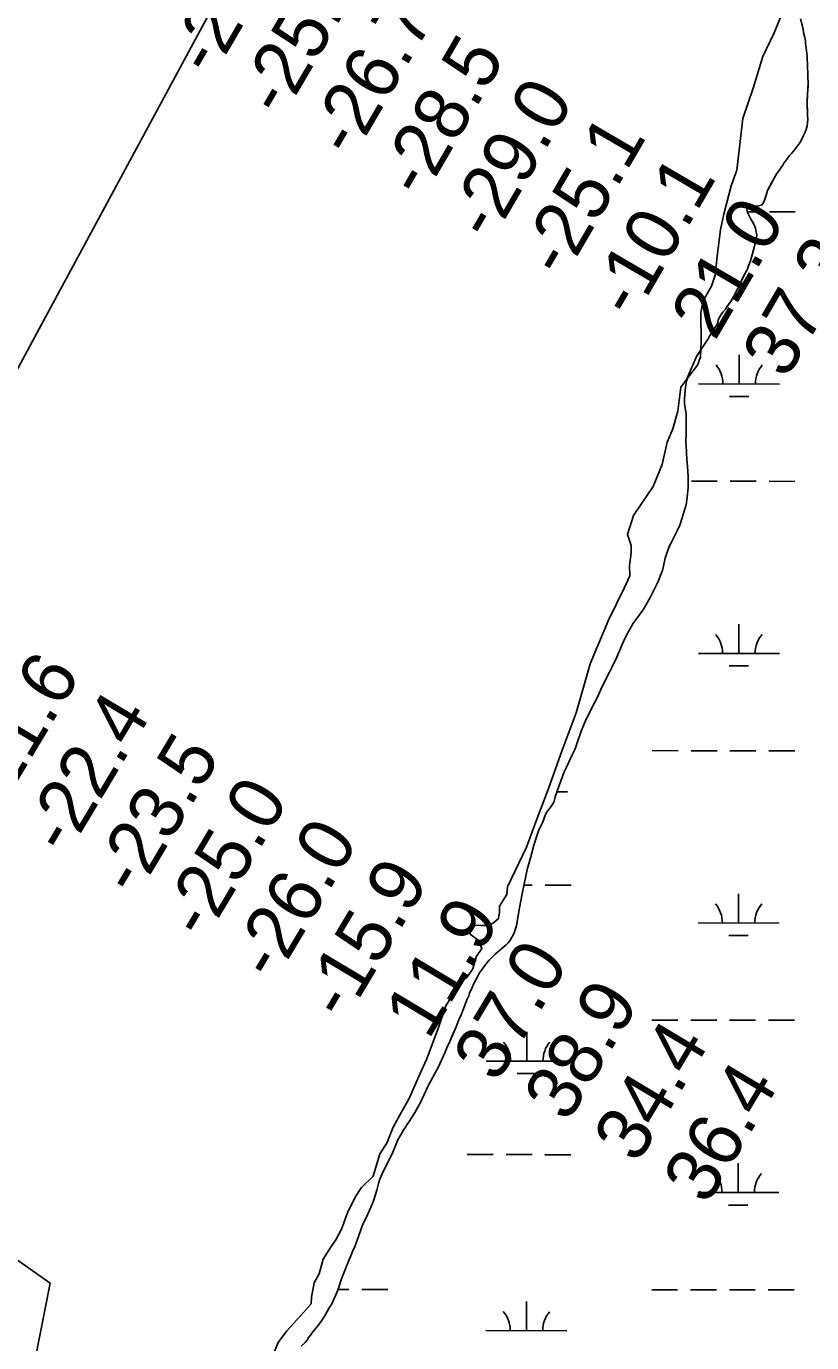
# Model space of a CAD drawing. Extents: x 3148686 to 3186545, y 916144 to 941516.
# Drawn here: x 3158993 to 3159963, y 925065 to 926690 of the extents above; entities that cross this region are included whole.
import ezdxf

# ---------------------------------------------------------------- set-up
doc = ezdxf.new("R2010")
doc.units = 0
for name, color, linetype in [('V-RIVR-EDGE', 7, 'Continuous'), ('V-RIVR-RANG', 7, 'Continuous'), ('V-SITE-VEGE', 7, 'Continuous'), ('V-TOPO-BNDY', 7, 'Continuous'), ('V-WETL-SWMP', 7, 'Continuous')]:
    doc.layers.add(name, color=color, linetype=linetype)

msp = doc.modelspace()

# ---------------------------------------------------------------- linework, layer by layer
at = {"layer": 'V-RIVR-EDGE'}
for points in [[(3159740.5, 926039.6), (3159740.2, 926049), (3159735.7, 926062.5), (3159743.4, 926085.9), (3159767.5, 926121.5), (3159778.5, 926148.8), (3159785, 926176.5), (3159792, 926193), (3159798.2, 926214.6), (3159801.6, 926244.4), (3159815.1, 926262.4), (3159822.1, 926271.2), (3159825.8, 926281.5), (3159826.7, 926299.8), (3159826.5, 926336.3), (3159829.3, 926350.9), (3159839.7, 926368.9), (3159844, 926382.6), (3159846.5, 926405.4), (3159850.8, 926438.9), (3159855.4, 926459.3), (3159863.7, 926492.8), (3159870.8, 926512), (3159878.3, 926575.9), (3159891.1, 926613.3), (3159902.8, 926652.6), (3159916.9, 926681.5), (3159931.9, 926718)], [(3159292.8, 925037.2), (3159304.4, 925065.2), (3159315.1, 925079.5), (3159332.2, 925098.3), (3159345, 925112.6), (3159345.7, 925121.1), (3159349, 925138.5), (3159355.2, 925149.7), (3159360.1, 925167.7), (3159369.9, 925183.5), (3159375.7, 925191.7), (3159382.7, 925204.8), (3159390.1, 925224.9), (3159399.3, 925244.3), (3159407.5, 925256.5), (3159421.9, 925270.2), (3159430.1, 925297.9), (3159438.7, 925311.2), (3159446.4, 925330.7), (3159457.7, 925351.1), (3159466.3, 925366.3), (3159477.6, 925392.5), (3159487.7, 925414.4), (3159501.8, 925452.4), (3159511.6, 925480.7), (3159523.8, 925500.5), (3159527.8, 925509.9), (3159537.3, 925515.4), (3159544.9, 925526.3), (3159548.9, 925541.2), (3159555.9, 925551.2), (3159550.8, 925562.2), (3159542, 925568.6), (3159540.2, 925574.1), (3159543.8, 925580.2), (3159555.4, 925579.9), (3159564.5, 925579.6), (3159570.3, 925583.2), (3159576.4, 925588.4), (3159577.7, 925596), (3159577.7, 925603.6), (3159586.6, 925618.2), (3159587.5, 925627.3), (3159611.1, 925676.3), (3159624.9, 925714.3), (3159637.7, 925747.8), (3159655.2, 925796.2), (3159672.4, 925842.4), (3159689.9, 925902.7), (3159712.3, 925956.5), (3159731.9, 925996.1), (3159738.6, 926011.3), (3159738.3, 926024.1), (3159740.5, 926039.6)]]:
    msp.add_lwpolyline(points, dxfattribs=at)
at = {"layer": 'V-SITE-VEGE'}
for points in [[(3159949.7, 926699), (3159952.8, 926686), (3159953.4, 926682), (3159954.9, 926675.8), (3159955.5, 926672.2), (3159955.5, 926668.6), (3159956.5, 926663), (3159957.6, 926652.8), (3159957.6, 926648.6), (3159958.1, 926643.8), (3159958.1, 926639), (3159958.5, 926631.8), (3159958.6, 926627.2), (3159959, 926620.2), (3159958.6, 926611.8), (3159958.3, 926606.3), (3159957.9, 926597.9), (3159957.6, 926591.9), (3159958.2, 926582.3), (3159958.2, 926579.3), (3159958.5, 926575.5), (3159958.3, 926570.1), (3159957.9, 926566.7), (3159956.7, 926562.3), (3159954.9, 926558.3), (3159953.2, 926555.1), (3159950.2, 926548.9), (3159948.6, 926546), (3159946.4, 926542.6), (3159943.3, 926538.8), (3159940.7, 926535.4), (3159935.7, 926529.6), (3159933.3, 926526.5), (3159929.1, 926520.7), (3159927.6, 926518.1), (3159925.6, 926515.5), (3159923.2, 926511.7), (3159920.4, 926508), (3159917, 926502.4), (3159908.9, 926486.8), (3159907, 926481.3), (3159905, 926475.1), (3159903.4, 926471.3), (3159901.2, 926469.1), (3159897.6, 926468.1), (3159894.2, 926467.7), (3159890.6, 926468), (3159886.6, 926468.2), (3159883.2, 926463.2), (3159884.1, 926459.8), (3159885.9, 926456.6), (3159887.7, 926452.6), (3159891.7, 926445.6), (3159893.8, 926440.4), (3159894.8, 926436), (3159895.4, 926432.2), (3159895.2, 926429), (3159893.5, 926421.6), (3159889.8, 926407.4), (3159887.6, 926400), (3159886.4, 926396.8), (3159885.2, 926393.9), (3159883.9, 926390.1), (3159882.3, 926386.9), (3159876.9, 926376.9), (3159873.8, 926369.3), (3159872, 926366.2)], [(3159872, 926366.2), (3159870.4, 926363.2), (3159867, 926356.4), (3159863.7, 926351), (3159858.9, 926344), (3159857.1, 926340.9), (3159853.7, 926336.9), (3159852, 926334.5), (3159850.2, 926331.7), (3159848, 926327.5), (3159847.4, 926323.7), (3159846, 926320.9), (3159844.1, 926318.1), (3159840.9, 926312.6), (3159837.3, 926307), (3159835.5, 926304), (3159827.1, 926291.7), (3159821.2, 926282), (3159819.6, 926278.1), (3159817.7, 926274.5), (3159816.4, 926271.4), (3159814.8, 926268), (3159810.1, 926256.3), (3159808.8, 926251.5), (3159807.5, 926244.8), (3159806.2, 926230.2), (3159806.1, 926226.6), (3159806.3, 926223.4), (3159808.2, 926211.3), (3159808.4, 926206.5), (3159808.1, 926203.3), (3159808.2, 926187.8), (3159808, 926176), (3159808.4, 926172.5), (3159808.6, 926163.5), (3159809.2, 926154.7), (3159809.6, 926151.5), (3159810.8, 926134.1), (3159810.6, 926120.6), (3159810, 926112.2), (3159809.5, 926108.3), (3159808.1, 926099.2), (3159807.2, 926095.3), (3159803.5, 926082.8), (3159800.6, 926074.1), (3159797.3, 926067), (3159789.6, 926052.2), (3159787.4, 926047.4), (3159786, 926044), (3159784.8, 926040.7), (3159782.3, 926033), (3159781, 926027.3), (3159780.3, 926023.1), (3159779, 926018.1), (3159777.2, 926013.2), (3159773.7, 926004.3), (3159763.8, 925984.7), (3159758.4, 925975), (3159755.6, 925970.4), (3159750.7, 925963.2), (3159748.7, 925960.3), (3159746.5, 925957.7), (3159742.5, 925951.9), (3159738.2, 925944.9), (3159736.1, 925940.9), (3159732.6, 925934), (3159729.2, 925926.6), (3159722.5, 925911.1), (3159716.7, 925899.2), (3159713.7, 925892.4), (3159704.3, 925873.9), (3159700.1, 925864.6), (3159697.1, 925858.2), (3159695, 925854.4), (3159687.7, 925840.3), (3159683.7, 925831.7), (3159678.8, 925819.5), (3159673, 925802.9), (3159671, 925798), (3159667.7, 925790.6), (3159661.2, 925776.8), (3159658.1, 925770.1), (3159656.5, 925766), (3159654.8, 925761.3), (3159653.6, 925758.5), (3159649.2, 925746.8), (3159646.5, 925738.6), (3159645.1, 925732.9), (3159643.8, 925730.1), (3159641.1, 925726.3), (3159638.5, 925723.1), (3159636, 925719.2), (3159633.8, 925714.6), (3159631.5, 925708.5), (3159626, 925696.6), (3159620.3, 925678.7), (3159617.4, 925667.8), (3159613.8, 925656), (3159612.2, 925650.4), (3159608.8, 925632.7), (3159605.7, 925618.8)], [(3159605.7, 925618.8), (3159602.3, 925601.6), (3159600.1, 925587), (3159598.8, 925579.5), (3159596.4, 925571.8), (3159594.5, 925567.7), (3159592.7, 925564.5), (3159590.4, 925561), (3159588.5, 925558.4), (3159586.1, 925555.7), (3159572.6, 925544.3), (3159565, 925537), (3159562.2, 925533.7), (3159553.2, 925521.3), (3159551.3, 925518.1), (3159545.7, 925507.3), (3159543.8, 925503.2), (3159540.9, 925496.1), (3159539.8, 925492.9), (3159537.9, 925488.8), (3159530.2, 925469.5), (3159527.4, 925463.2), (3159524.1, 925454.8), (3159515.6, 925434.5), (3159513.7, 925430.6), (3159510.4, 925422.7), (3159504.2, 925409.1), (3159502, 925404.6), (3159498.2, 925397.9), (3159489.3, 925380.9), (3159484.5, 925371), (3159480.4, 925362), (3159477, 925355.4), (3159472.7, 925348), (3159470.8, 925344.9), (3159459.3, 925327.3), (3159452.3, 925315.2), (3159445, 925297.7), (3159434.4, 925276.7), (3159430.1, 925266.8), (3159428.2, 925261.1), (3159426.2, 925253), (3159422.9, 925242.5), (3159420.7, 925236.6), (3159413, 925218.9), (3159409.1, 925210.9), (3159398.9, 925183.2), (3159397.1, 925179.2), (3159394.2, 925171.8), (3159392.5, 925168.1), (3159382.7, 925143.5), (3159379.8, 925134.6), (3159377.1, 925127.7), (3159370.3, 925112.1), (3159367.5, 925107.7), (3159362.5, 925098.6), (3159357.9, 925091.6), (3159353.7, 925085.9), (3159347.4, 925078.3), (3159344.6, 925074.4), (3159342.4, 925071.4), (3159340.2, 925067.8), (3159337.9, 925065.2), (3159332.9, 925060.5)]]:
    msp.add_lwpolyline(points, dxfattribs=at)
at = {"layer": 'V-TOPO-BNDY'}
for points in [[(3156122.4, 922098.2), (3156168.8, 922145.8), (3156428.7, 922411), (3156852.6, 922931.2), (3157254.5, 923382.8), (3157305.3, 923439.5), (3157317.3, 923453.1), (3157677.4, 924009.7), (3157746.6, 924116.6), (3157949.7, 924442.8), (3158078.5, 924650.3), (3158117.2, 924712.4), (3158363.3, 925108.2), (3158430.5, 925235.2), (3158537.2, 925435.5), (3158721.6, 925781.3), (3158837.1, 925997.9), (3159006.2, 926311.1), (3159280.9, 926819.7)], [(3160847.8, 924177.7), (3160641.8, 924139.1), (3160353.9, 924087.6), (3159860.3, 924136.3), (3159704.5, 924185.6), (3159392.9, 924289), (3159085.6, 924463), (3159034.9, 924602.9), (3159010.3, 924670.5), (3159009.3, 924692.2), (3159000.3, 924860.7), (3158993.7, 924989.2), (3159003.7, 925042.2), (3159022.8, 925138.1), (3158942.3, 925194.8), (3158717.5, 925353), (3158537.2, 925435.5)]]:
    msp.add_lwpolyline(points, dxfattribs=at)
at = {"layer": 'V-WETL-SWMP'}
for p, q in [((3159883.8, 926460.8), (3159895.1, 926460.8)), ((3159911.1, 926460.8), (3159943.1, 926460.7)), ((3159873.7, 926248.2), (3159873.7, 926284.2)), ((3159823.7, 926248.2), (3159923.7, 926248.1)), ((3159861.7, 926232.8), (3159885.7, 926232.7)), ((3159814.7, 926128.2), (3159846.7, 926128.1)), ((3159862.7, 926128.1), (3159894.7, 926128.1)), ((3159910.7, 926128.1), (3159942.7, 926128)), ((3159873.4, 925915.5), (3159873.4, 925951.5)), ((3159823.4, 925915.6), (3159923.4, 925915.5)), ((3159861.3, 925900.1), (3159885.3, 925900.1)), ((3159766.4, 925795.6), (3159798.4, 925795.5)), ((3159814.4, 925795.5), (3159846.4, 925795.5)), ((3159862.4, 925795.5), (3159894.4, 925795.4)), ((3159910.4, 925795.4), (3159942.4, 925795.4)), ((3159648.6, 925744.9), (3159661.7, 925744.9)), ((3159608.1, 925629.5), (3159618.2, 925629.5)), ((3159634.2, 925629.5), (3159666.2, 925629.5)), ((3159873, 925582.8), (3159873, 925618.8)), ((3159823, 925582.9), (3159923, 925582.8)), ((3159861, 925567.4), (3159885, 925567.4)), ((3159611.4, 925412.3), (3159611.4, 925448.3)), ((3159766, 925462.9), (3159798, 925462.8)), ((3159814, 925462.8), (3159846, 925462.8)), ((3159862, 925462.8), (3159894, 925462.7)), ((3159910, 925462.7), (3159942, 925462.7)), ((3159561.4, 925412.4), (3159661.4, 925412.2)), ((3159599.4, 925396.9), (3159623.4, 925396.9)), ((3159537.9, 925296.9), (3159569.9, 925296.9)), ((3159585.9, 925296.9), (3159617.9, 925296.9)), ((3159633.9, 925296.8), (3159665.9, 925296.8)), ((3159872.7, 925250.2), (3159872.7, 925286.2)), ((3159822.7, 925250.2), (3159922.7, 925250.1)), ((3159860.6, 925234.7), (3159884.6, 925234.7)), ((3159378.2, 925130.6), (3159391.8, 925130.6)), ((3159407.8, 925130.6), (3159439.8, 925130.6)), ((3159765.7, 925130.2), (3159797.7, 925130.2)), ((3159813.7, 925130.2), (3159845.7, 925130.1)), ((3159861.7, 925130.1), (3159893.7, 925130.1)), ((3159909.7, 925130.1), (3159941.7, 925130)), ((3159611, 925079.6), (3159611.1, 925115.6)), ((3159561, 925079.7), (3159661, 925079.6))]:
    msp.add_line(p, q, dxfattribs=at)
for points in [[(3159951, 926693.6), (3159952, 926689.2), (3159952.8, 926686), (3159953.4, 926682), (3159954.9, 926675.8), (3159955.5, 926672.2), (3159955.5, 926668.6), (3159956.5, 926663), (3159957, 926659.2), (3159957.6, 926652.8), (3159957.6, 926648.6), (3159958.1, 926643.8), (3159958.1, 926639), (3159958.5, 926631.8), (3159958.6, 926627.2), (3159959, 926620.2), (3159958.8, 926616.2), (3159958.6, 926611.8), (3159958.3, 926606.3), (3159958.1, 926602.7), (3159957.9, 926597.9), (3159957.6, 926591.9), (3159958, 926586.3), (3159958.2, 926582.3), (3159958.2, 926579.3), (3159958.5, 926575.5), (3159958.3, 926570.1), (3159957.9, 926566.7), (3159956.7, 926562.3), (3159954.9, 926558.3), (3159953.2, 926555.1), (3159950.2, 926548.9), (3159948.6, 926546), (3159946.4, 926542.6), (3159943.3, 926538.8), (3159940.7, 926535.4), (3159938.7, 926533), (3159935.7, 926529.6), (3159933.3, 926526.5), (3159929.1, 926520.7), (3159927.6, 926518.1), (3159925.6, 926515.5), (3159923.2, 926511.7)], [(3159923.2, 926511.7), (3159920.4, 926508), (3159917, 926502.4), (3159914.5, 926497.4), (3159912.3, 926493.4), (3159910.7, 926490.2), (3159908.9, 926486.8), (3159907, 926481.3), (3159905, 926475.1), (3159903.4, 926471.3), (3159901.2, 926469.1), (3159897.6, 926468.1), (3159894.2, 926467.7), (3159890.6, 926468), (3159886.6, 926468.2), (3159883.2, 926463.2), (3159884.1, 926459.8), (3159885.9, 926456.6), (3159887.7, 926452.6), (3159889.7, 926449.2), (3159891.7, 926445.6), (3159893.8, 926440.4), (3159894.8, 926436), (3159895.4, 926432.2), (3159895.2, 926429), (3159894.5, 926425.8), (3159893.5, 926421.6), (3159892.1, 926416.6), (3159890.6, 926410.4), (3159889.8, 926407.4), (3159887.6, 926400), (3159886.4, 926396.8), (3159885.2, 926393.9), (3159883.9, 926390.1), (3159882.3, 926386.9), (3159880.1, 926382.9), (3159876.9, 926376.9), (3159873.8, 926369.3), (3159872, 926366.2), (3159870.4, 926363.2), (3159867, 926356.4), (3159863.7, 926351), (3159861.3, 926347.4), (3159858.9, 926344), (3159857.1, 926340.9), (3159853.7, 926336.9), (3159852, 926334.5), (3159850.2, 926331.7), (3159848, 926327.5), (3159847.4, 926323.7), (3159846, 926320.9), (3159844.1, 926318.1), (3159840.9, 926312.6), (3159837.3, 926307), (3159835.5, 926304), (3159827.1, 926291.7), (3159821.2, 926282), (3159819.6, 926278.1), (3159817.7, 926274.5), (3159816.4, 926271.4), (3159814.8, 926268), (3159810.1, 926256.3), (3159808.8, 926251.5), (3159807.5, 926244.8), (3159806.2, 926230.2), (3159806.1, 926226.6), (3159806.3, 926223.4), (3159808.2, 926211.3), (3159808.4, 926206.5), (3159808.1, 926203.3), (3159808.2, 926187.8), (3159808, 926176), (3159808.4, 926172.5), (3159808.6, 926163.5), (3159809.2, 926154.7), (3159809.6, 926151.5), (3159810.8, 926134.1), (3159810.6, 926120.6), (3159810, 926112.2), (3159809.5, 926108.3), (3159808.1, 926099.2), (3159807.2, 926095.3), (3159803.5, 926082.8), (3159800.6, 926074.1), (3159797.3, 926067), (3159789.6, 926052.2), (3159787.4, 926047.4), (3159786, 926044), (3159784.8, 926040.7), (3159782.3, 926033), (3159781, 926027.3), (3159780.3, 926023.1), (3159779, 926018.1), (3159777.2, 926013.2), (3159773.7, 926004.3), (3159763.8, 925984.7), (3159758.4, 925975), (3159755.6, 925970.4), (3159750.7, 925963.2), (3159748.7, 925960.3), (3159746.5, 925957.7)], [(3159746.5, 925957.7), (3159742.5, 925951.9), (3159738.2, 925944.9), (3159736.1, 925940.9), (3159732.6, 925934), (3159729.2, 925926.6), (3159722.5, 925911.1), (3159716.7, 925899.2), (3159713.7, 925892.4), (3159704.3, 925873.9), (3159700.1, 925864.6), (3159697.1, 925858.2), (3159695, 925854.4), (3159687.7, 925840.3), (3159683.7, 925831.7), (3159678.8, 925819.5), (3159673, 925802.9), (3159671, 925798), (3159667.7, 925790.6), (3159661.2, 925776.8), (3159658.1, 925770.1), (3159656.5, 925766), (3159654.8, 925761.3), (3159653.6, 925758.5), (3159649.2, 925746.8), (3159646.5, 925738.6), (3159645.1, 925732.9), (3159643.8, 925730.1), (3159641.1, 925726.3), (3159638.5, 925723.1), (3159636, 925719.2), (3159633.8, 925714.6), (3159631.5, 925708.5), (3159626, 925696.6), (3159620.3, 925678.7), (3159617.4, 925667.8), (3159613.8, 925656), (3159612.2, 925650.4), (3159608.8, 925632.7), (3159605.7, 925618.8), (3159602.3, 925601.6), (3159600.1, 925587), (3159598.8, 925579.5), (3159596.4, 925571.8), (3159594.5, 925567.7), (3159592.7, 925564.5), (3159590.4, 925561), (3159588.5, 925558.4), (3159586.1, 925555.7), (3159572.6, 925544.3), (3159565, 925537), (3159562.2, 925533.7), (3159553.2, 925521.3), (3159551.3, 925518.1), (3159545.7, 925507.3), (3159543.8, 925503.2), (3159540.9, 925496.1), (3159539.8, 925492.9), (3159537.9, 925488.8), (3159530.2, 925469.5), (3159527.4, 925463.2), (3159524.1, 925454.8), (3159519, 925442.6), (3159515.6, 925434.5), (3159513.7, 925430.6), (3159510.4, 925422.7), (3159504.2, 925409.1), (3159502, 925404.6), (3159498.2, 925397.9), (3159489.3, 925380.9), (3159484.5, 925371), (3159480.4, 925362), (3159477, 925355.4), (3159472.7, 925348), (3159470.8, 925344.9), (3159459.3, 925327.3), (3159452.3, 925315.2), (3159445, 925297.7), (3159434.4, 925276.7), (3159430.1, 925266.8), (3159428.2, 925261.1), (3159426.2, 925253), (3159422.9, 925242.5), (3159420.7, 925236.6), (3159413, 925218.9), (3159409.1, 925210.9), (3159398.9, 925183.2), (3159397.1, 925179.2), (3159394.2, 925171.8), (3159392.5, 925168.1), (3159382.7, 925143.5), (3159379.8, 925134.6), (3159377.1, 925127.7), (3159370.3, 925112.1), (3159367.5, 925107.7), (3159362.5, 925098.6), (3159357.9, 925091.6), (3159353.7, 925085.9), (3159347.4, 925078.3), (3159344.6, 925074.4), (3159342.4, 925071.4)], [(3159342.4, 925071.4), (3159340.2, 925067.8), (3159337.9, 925065.2), (3159332.9, 925060.5)]]:
    msp.add_lwpolyline(points, dxfattribs=at)
for centre, start, end in [((3159818.5, 926248.7), 359.1678, 40.7115), ((3159929, 926248.6), 139.1678, 180.7115), ((3159818.1, 925916), 359.1678, 40.7115), ((3159928.6, 925915.9), 139.1678, 180.7115), ((3159817.8, 925583.4), 359.1678, 40.7115), ((3159928.3, 925583.3), 139.1678, 180.7115), ((3159556.2, 925412.8), 359.1678, 40.7115), ((3159666.6, 925412.7), 139.1678, 180.7115), ((3159817.4, 925250.7), 359.1678, 40.7115), ((3159927.9, 925250.6), 139.1678, 180.7115), ((3159555.8, 925080.2), 359.1678, 40.7115), ((3159666.3, 925080), 139.1678, 180.7115)]:
    msp.add_arc(centre, 35.2, start, end, dxfattribs=at)

# ---------------------------------------------------------------- texts
at = {"layer": 'V-RIVR-RANG'}
for s, rotation, p in [('-25.7', 59.7183, (3159223.2, 926625.5)), ('-25.5', 59.7183, (3159309.7, 926575.3)), ('-26.7', 59.7183, (3159396.2, 926525.1)), ('-28.5', 59.7183, (3159482.6, 926474.9)), ('-29.0', 59.7183, (3159567.6, 926422.1)), ('-25.1', 59.7183, (3159656.8, 926376.5)), ('-10.1', 59.7183, (3159743.3, 926326.3)), ('21.0', 59.7183, (3159843.8, 926300.2)), ('37.3', 59.7183, (3159931.8, 926252.5)), ('-21.6', 59.1383, (3158956.4, 925713.9)), ('-22.4', 59.1383, (3159043.3, 925664.4)), ('-23.5', 59.1383, (3159129.2, 925613.3)), ('-25.0', 59.1383, (3159213.7, 925559.8)), ('-26.0', 59.1383, (3159299.7, 925508.7)), ('-15.9', 59.1383, (3159387, 925459.8)), ('11.9', 59.1383, (3159490, 925437.3)), ('37.0', 59.1383, (3159574.6, 925383.9)), ('38.9', 59.1383, (3159661.9, 925335.1)), ('34.4', 59.1383, (3159748, 925284.2)), ('36.4', 59.1383, (3159834, 925233.1))]:
    msp.add_text(s, height=67, rotation=rotation, dxfattribs=at).set_placement(p)

doc.saveas('drawing.dxf')
